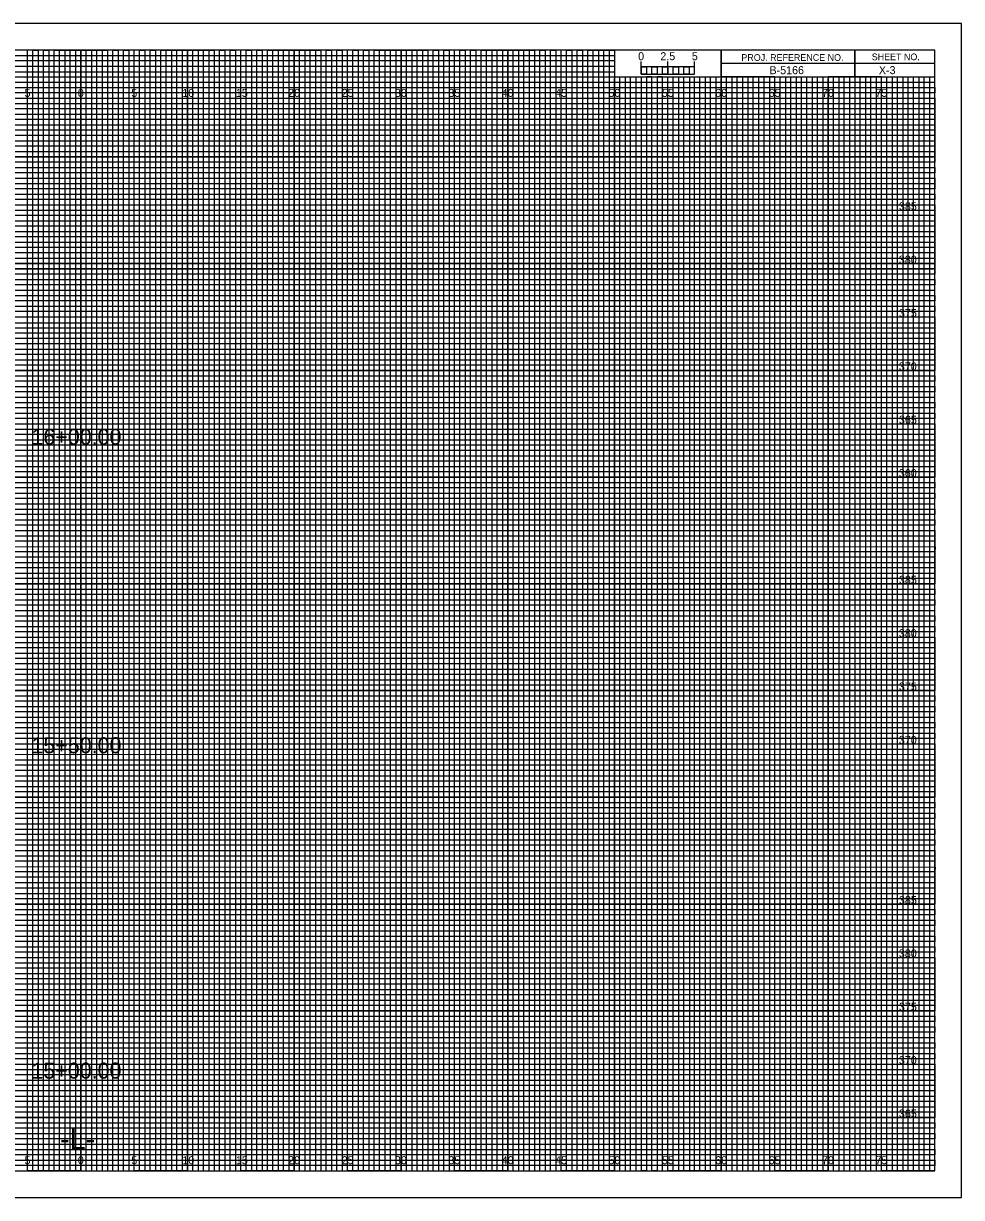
# Model space of a CAD drawing. Extents: x -8 to 162, y 218 to 328.
# Drawn here: x 74.6 to 162.5, y 217.5 to 327.5 of the extents above; entities that cross this region are included whole.
import ezdxf

# ---------------------------------------------------------------- set-up
doc = ezdxf.new("R2010")
doc.units = 0
for name, color, linetype in [('Cored Slab Unit CELL', 7, 'Continuous'), ('Exist XS Center Line Elevation Label', 7, 'Continuous'), ('Exist XS Ground Line', 7, 'Continuous'), ('Prop CMT Guardrail Graphics', 7, 'Continuous'), ('Prop CMT Pvmt Surface', 7, 'Continuous'), ('Prop CMT Pvmt Surface Shoulder', 7, 'Continuous'), ('Prop CMT Slope Grass', 7, 'Continuous'), ('Prop CMT Subgrade Earthwork', 7, 'Continuous'), ('Prop XS Berm Ditch', 7, 'Continuous'), ('Prop XS Finish Grade Earthwork', 7, 'Continuous'), ('Scratch_Level_0', 7, 'Continuous'), ('Scratch_Level_1', 7, 'Continuous'), ('Scratch_Level_2', 7, 'Continuous'), ('Sheet Cross Section Scale CELL', 7, 'Continuous'), ('Typical Curb CELL', 7, 'Continuous')]:
    doc.layers.add(name, color=color, linetype=linetype)

msp = doc.modelspace()

# ---------------------------------------------------------------- linework, layer by layer
at = {"layer": 'Exist XS Center Line Elevation Label'}
for points in [[(72.5, 220), (77.5, 220), (77.5, 325), (82.5, 325), (82.5, 220), (87.5, 220), (87.5, 325), (92.5, 325), (92.5, 220), (97.5, 220), (97.5, 325), (102.5, 325), (102.5, 220), (107.5, 220), (107.5, 325), (112.5, 325), (112.5, 220), (117.5, 220), (117.5, 325), (122.5, 325), (122.5, 220), (127.5, 220), (127.5, 325), (129.97, 325), (130, 325), (130, 322.5), (132.5, 322.5), (132.5, 220), (137.5, 220), (137.5, 322.5), (142.5, 322.5), (142.5, 220), (147.5, 220), (147.5, 322.5), (152.5, 322.5), (152.5, 220), (157.5, 220), (157.5, 322.5)], [(0, 322.5), (137.5, 322.5)], [(0, 312.5), (160, 312.5), (160, 317.5), (0, 317.5)], [(0, 302.5), (160, 302.5), (160, 307.5), (0, 307.5)], [(0, 292.5), (160, 292.5), (160, 297.5), (0, 297.5)], [(0, 282.5), (160, 282.5), (160, 287.5), (0, 287.5)], [(0, 272.5), (160, 272.5), (160, 277.5), (0, 277.5)], [(0, 262.5), (160, 262.5), (160, 267.5), (0, 267.5)], [(0, 252.5), (160, 252.5), (160, 257.5), (0, 257.5)], [(0, 242.5), (160, 242.5), (160, 247.5), (0, 247.5)], [(0, 232.5), (160, 232.5), (160, 237.5), (0, 237.5)], [(0, 222.5), (160, 222.5), (160, 227.5), (0, 227.5)]]:
    msp.add_lwpolyline(points, dxfattribs=at)
at = {"layer": 'Exist XS Ground Line'}
for p, q in [((75, 325), (70, 325)), ((75, 220), (75, 325)), ((85, 325), (80, 325)), ((80, 325), (80, 220)), ((85, 220), (85, 325)), ((95, 325), (90, 325)), ((90, 325), (90, 220)), ((95, 220), (95, 325)), ((105, 325), (100, 325)), ((100, 325), (100, 220)), ((105, 220), (105, 325)), ((115, 325), (110, 325)), ((110, 325), (110, 220)), ((115, 220), (115, 325)), ((125, 325), (120, 325)), ((120, 325), (120, 220)), ((125, 220), (125, 325)), ((130, 325), (130, 220)), ((135, 220), (135, 322.5)), ((145, 322.5), (140, 322.5)), ((140, 322.5), (140, 220)), ((145, 220), (145, 322.5)), ((155, 322.5), (150, 322.5)), ((150, 322.5), (150, 220)), ((155, 220), (155, 322.5)), ((80, 220), (75, 220)), ((90, 220), (85, 220)), ((100, 220), (95, 220)), ((110, 220), (105, 220)), ((120, 220), (115, 220)), ((130, 220), (125, 220)), ((140, 220), (135, 220)), ((150, 220), (145, 220)), ((160, 220), (155, 220)), ((160, 220), (160, 220))]:
    msp.add_line(p, q, dxfattribs=at)
for points in [[(0, 320), (160, 320), (160, 315), (0, 315)], [(0, 310), (160, 310), (160, 305), (0, 305)], [(0, 300), (160, 300), (160, 295), (0, 295)], [(0, 290), (160, 290), (160, 285), (0, 285)], [(0, 280), (160, 280), (160, 275), (0, 275)], [(0, 270), (160, 270), (160, 265), (0, 265)], [(0, 260), (160, 260), (160, 255), (0, 255)], [(0, 250), (160, 250), (160, 245), (0, 245)], [(0, 240), (160, 240), (160, 235), (0, 235)], [(0, 230), (160, 230), (160, 225), (0, 225)]]:
    msp.add_lwpolyline(points, dxfattribs=at)
at = {"layer": 'Prop CMT Subgrade Earthwork'}
msp.add_lwpolyline([(-7.5, 217.5), (162.5, 217.5), (162.5, 327.5), (-7.5, 327.5)], close=True, dxfattribs=at)
at = {"layer": 'Prop XS Berm Ditch'}
for p, q in [((0, 324.5), (130, 324.5)), ((130, 324.5), (130, 323.99)), ((130, 323.99), (0, 323.99)), ((0, 323.5), (130, 323.5)), ((130, 323.5), (130, 322.94)), ((130, 322.94), (0, 322.94)), ((0, 322), (160, 322))]:
    msp.add_line(p, q, dxfattribs=at)
for points in [[(0, 321.5), (135, 321.5), (160, 321.5), (160, 321), (0, 321)], [(0, 320.5), (160, 320.5), (160, 319.5), (0, 319.5)], [(0, 319), (160, 319), (160, 318.5), (0, 318.49)], [(0, 318), (160, 318), (160, 317), (0, 317)], [(0, 316.5), (160, 316.5), (160, 316), (0, 316)], [(0, 315.5), (160, 315.5), (160, 314.5), (0, 314.5)], [(0, 314), (160, 314), (160, 313.5), (0, 313.5)], [(0, 313), (160, 313), (160, 312), (0, 312)], [(0, 311.5), (160, 311.5), (160, 311), (0, 311)], [(0, 310.5), (160, 310.5), (160, 309.5), (0, 309.5)], [(0, 309), (160, 309), (160, 308.5), (0, 308.5)], [(0, 308), (160, 308), (160, 306.98), (160, 306.5), (160, 306), (0, 306)], [(0, 307), (160, 307), (160, 306.5), (0, 306.5)], [(0, 305.5), (160, 305.5), (160, 304.5), (0, 304.51)], [(0, 304.51), (160, 304.5), (160, 304), (0, 304)], [(0, 303.5), (160, 303.5), (160, 303), (0, 303)], [(0, 302), (160, 302), (160, 301.5), (0, 301.5)], [(0, 301), (160, 301), (160, 300.5), (0, 300.5)], [(-0.04, 299.44), (160, 299.44), (160, 298.94), (-0.04, 298.94)], [(0, 298.5), (160, 298.5), (160, 298), (0, 298)], [(0, 297), (160, 297), (160, 296.5), (0, 296.5)], [(0, 296), (160, 296), (160, 295.5), (0, 295.5)], [(0, 294.5), (160, 294.5), (160, 294), (0, 294)], [(0, 293.5), (160, 293.5), (160, 293), (0, 293)], [(0, 292), (160, 292), (160, 291.5), (0, 291.5)], [(0, 291), (160, 291), (160, 290.5), (0, 290.5)], [(0, 289.5), (160, 289.5), (160, 288.99), (0, 289)], [(0, 288.5), (160, 288.5), (160, 288), (0, 288)], [(0, 287), (160, 287), (160, 286.5), (0, 286.5)], [(0, 286), (160, 286), (160, 285.5), (0, 285.5)], [(0, 284.5), (160, 284.5), (160, 284), (0, 284)], [(0, 283.5), (160, 283.5), (160, 283), (0, 283)], [(0, 282), (160, 282), (160, 281.5), (0, 281.5)], [(0, 281), (160, 281), (160, 280.5), (0, 280.5)], [(0, 279.5), (160, 279.5), (160, 279), (0, 279)], [(0, 278.5), (160.03, 278.45), (160, 278), (0, 278)], [(0, 277), (160, 277), (160, 276.5), (0, 276.5)], [(0, 276), (160, 276), (160, 275.5), (0, 275.5)], [(0, 274.5), (160, 274.5), (160, 274), (0, 274)], [(0, 273.5), (160, 273.5), (160, 273), (0, 273)], [(0, 272), (160, 272), (160, 271.5), (0, 271.5)], [(0, 271), (160, 271), (160, 270.5), (0, 270.5)], [(0, 269.5), (160, 269.5), (160, 269), (0, 269)], [(0, 268.5), (160, 268.5), (160, 268), (0, 268)], [(0, 267), (160, 267), (160, 266.5), (0, 266.5)], [(0, 266), (160, 266), (160, 265.5), (0, 265.5)], [(0, 264.5), (160, 264.5), (160, 264), (0, 264)], [(0, 263.5), (160, 263.5), (160, 263), (0, 263)], [(0, 262), (160, 262), (160, 261.5), (0, 261.5)], [(0, 261), (160, 261), (160, 260.5), (0, 260.5)], [(0, 259.5), (160, 259.5), (160, 258.99), (0, 259)], [(0, 258.5), (160, 258.5), (160, 258), (0, 258)], [(0, 257), (160, 257), (160, 256.5), (0, 256.5)], [(0, 256), (160, 256), (160, 255.5), (0, 255.5)], [(0, 254.5), (160, 254.5), (160, 254), (0, 254)], [(0, 253.5), (160, 253.5), (160, 253), (0, 253)], [(0, 252), (160, 252), (160, 251.5), (0, 251.5)], [(0, 251), (160, 251), (160, 250.5), (0, 250.5)], [(0, 249.5), (160, 249.5), (160, 249), (0, 249)], [(0, 248.5), (160.03, 248.46), (160, 248), (0, 248)], [(0, 247), (160, 247), (160, 246.5), (0, 246.5)], [(0, 246), (160, 246), (160, 245.5), (0, 245.5)], [(0, 244.5), (160, 244.5), (160, 244), (0, 244)], [(0, 243.5), (160, 243.5), (160, 243), (0, 243)], [(0, 242), (160, 242), (160, 241.5), (0, 241.5)], [(0, 241), (160, 241), (160, 240.5), (0, 240.5)], [(0, 239.5), (160, 239.5), (160, 239), (0, 239)], [(0, 238.5), (160, 238.5), (160, 238), (0, 238)], [(0, 237), (160, 237), (160, 236.5), (0, 236.5)], [(0, 236), (160, 236), (160, 235.5), (0, 235.5)], [(0, 234.5), (160, 234.5), (160, 234), (0, 234)], [(0, 233.5), (160, 233.5), (160, 233), (0, 233)], [(0, 232), (160, 232), (160, 231.5), (0, 231.5)], [(0, 231), (160, 231), (160, 230.5), (0, 230.5)], [(0, 229.5), (160, 229.5), (160, 229), (0, 229)], [(0, 228.5), (160, 228.5), (160, 228), (0, 228)], [(0, 227), (160, 227), (160, 226.5), (0, 226.5)], [(0, 226), (160, 226), (160, 225.5), (0, 225.5)], [(0, 224.5), (160, 224.5), (160, 224), (0, 224)], [(0, 223.5), (160, 223.5), (160, 223), (0, 223)], [(0, 222), (160, 222), (160, 221.5), (0, 221.5)], [(0, 221), (160, 221), (160, 220.5), (0, 220.5)]]:
    msp.add_lwpolyline(points, dxfattribs=at)
at = {"layer": 'Scratch_Level_1'}
for p, q in [((133.5, 322.5), (133, 322.5)), ((133, 322.5), (133, 220)), ((133.5, 220), (133.5, 322.5)), ((134.5, 322.5), (134, 322.5)), ((134, 322.5), (134, 220)), ((134.5, 220), (134.5, 322.5)), ((133, 220), (132.5, 220)), ((134, 220), (133.5, 220))]:
    msp.add_line(p, q, dxfattribs=at)
for points in [[(75, 220), (75.5, 220), (75.5, 325), (76, 325), (76, 220)], [(76, 220), (76.5, 220), (76.5, 325), (77, 325), (77, 220)], [(77.5, 220), (78, 220), (78, 325), (78.5, 325), (78.5, 220)], [(78.5, 220), (79, 220), (79, 325), (79.5, 325), (79.5, 220)], [(80, 220), (80.5, 220), (80.5, 325), (81, 325), (81, 220)], [(81, 220), (81.5, 220), (81.5, 325), (82, 325), (82, 220)], [(82.5, 220), (83, 220), (83, 325), (83.5, 325), (83.5, 220)], [(83.5, 220), (84, 220), (84, 325), (84.5, 325), (84.5, 220)], [(85, 220), (85.5, 220), (85.5, 325), (86, 325), (86, 220)], [(86, 220), (86.5, 220), (86.5, 325), (87, 325), (87, 220)], [(87.5, 220), (88, 220), (88, 325), (88.5, 325), (88.5, 220)], [(88.5, 220), (89, 220), (89, 325), (89.5, 325), (89.5, 220)], [(90, 220), (90.5, 220), (90.5, 325), (91, 325), (91, 220)], [(91, 220), (91.5, 220), (91.5, 325), (92, 325), (92, 220)], [(92.5, 220), (93, 220), (93, 325), (93.5, 325), (93.5, 220)], [(93.5, 220), (94, 220), (94, 325), (94.5, 325), (94.5, 220)], [(95, 220), (95.5, 220), (95.5, 325), (96, 325), (96, 220)], [(96, 220), (96.5, 220), (96.5, 325), (97, 325), (97, 220)], [(97.5, 220), (98, 220), (98, 325), (98.5, 325), (98.5, 220)], [(98.5, 220), (99, 220), (99, 325), (99.5, 325), (99.5, 220)], [(100, 220), (100.5, 220), (100.5, 325), (101, 325), (101, 220)], [(101, 220), (101.5, 220), (101.5, 325), (102, 325), (102, 220)], [(102.5, 220), (103, 220), (103, 325), (103.5, 325), (103.5, 220)], [(103.5, 220), (104, 220), (104, 325), (104.5, 325), (104.5, 220)], [(105, 220), (105.5, 220), (105.5, 325), (106, 325), (106, 220)], [(106, 220), (106.5, 220), (106.5, 325), (107, 325), (107, 220)], [(107.5, 220), (108, 220), (108, 325), (108.5, 325), (108.5, 220)], [(108.5, 220), (109, 220), (109, 325), (109.5, 325), (109.5, 220)], [(110, 220), (110.5, 220), (110.5, 325), (111, 325), (111, 220)], [(111, 220), (111.5, 220), (111.5, 325), (112, 325), (112, 220)], [(112.5, 220), (113, 220), (113, 325), (113.5, 325), (113.5, 220)], [(113.5, 220), (114, 220), (114, 325), (114.5, 325), (114.5, 220)], [(115, 220), (115.5, 220), (115.5, 325), (116, 325), (116, 220)], [(116, 220), (116.5, 220), (116.5, 325), (117, 325), (117, 220)], [(117.5, 220), (118, 220), (118, 325), (118.5, 325), (118.5, 220)], [(118.5, 220), (119, 220), (119, 325), (119.5, 325), (119.5, 220)], [(120, 220), (120.5, 220), (120.5, 325), (121, 325), (121, 220)], [(121, 220), (121.5, 220), (121.5, 325), (122, 325), (122, 220)], [(122.5, 220), (123, 220), (123, 325), (123.5, 325), (123.5, 220)], [(123.5, 220), (124, 220), (124, 325), (124.5, 325), (124.5, 220)], [(125, 220), (125.5, 220), (125.5, 325), (126, 325), (126, 220)], [(126, 220), (126.5, 220), (126.5, 325), (127, 325), (127, 220)], [(127.5, 220), (128, 220), (128, 325), (128.5, 325), (128.5, 220)], [(128.5, 220), (129, 220), (129, 325), (129.5, 325), (129.5, 220)], [(130, 220), (130.5, 220), (130.5, 322.5), (131.01, 322.5), (131.01, 220)], [(131, 220), (131.5, 220), (131.5, 322.5), (132, 322.5), (132, 220)], [(135, 220), (135.49, 220), (135.49, 322.5), (136, 322.5), (136, 220)], [(136, 220), (136.5, 220), (136.5, 322.5), (137.03, 322.5), (137.03, 220)], [(137.5, 220), (138, 220), (138, 322.5), (138.5, 322.5), (138.5, 220)], [(138.5, 220), (139, 220), (139, 322.5), (139.5, 322.5), (139.5, 220)], [(140, 220), (140.5, 220), (140.5, 322.5), (141, 322.5), (141, 220)], [(141, 220), (141.5, 220), (141.5, 322.5), (142, 322.5), (142, 220)], [(142.5, 220), (143, 220), (143, 322.5), (143.5, 322.5), (143.5, 220)], [(143.5, 220), (144, 220), (144, 322.5), (144.5, 322.5), (144.5, 220)], [(145, 220), (145.5, 220), (145.5, 322.5), (146, 322.5), (146, 220)], [(146, 220), (146.5, 220), (146.5, 322.5), (147, 322.5), (147, 220)], [(147.5, 220), (148, 220), (148, 322.5), (148.5, 322.5), (148.5, 220)], [(148.5, 220), (149, 220), (149, 322.5), (149.5, 322.5), (149.5, 220)], [(150, 220), (150.5, 220), (150.5, 322.5), (151, 322.5), (151, 220)], [(151, 220), (151.5, 220), (151.5, 322.5), (152, 322.5), (152, 220)], [(152.5, 220), (153, 220), (153, 322.5), (153.5, 322.5), (153.5, 220)], [(153.5, 220), (154, 220), (154, 322.5), (154.5, 322.5), (154.5, 220)], [(155, 220), (155.5, 220), (155.5, 322.5), (156, 322.5), (156, 220)], [(156, 220), (156.5, 220), (156.5, 322.5), (157, 322.5), (157, 220)], [(157.5, 220), (158, 220), (158, 322.5), (158.5, 322.5), (158.5, 220)], [(158.5, 220), (159, 220), (159, 322.5), (159.5, 322.5), (159.5, 220)]]:
    msp.add_lwpolyline(points, dxfattribs=at)
at = {"layer": 'Scratch_Level_2'}
for p, q in [((75, 220), (75, 325)), ((80, 220), (80, 325)), ((85, 220), (85, 325)), ((90, 220), (90, 325)), ((95, 220), (95, 325)), ((100, 220), (100, 325)), ((105, 220), (105, 325)), ((110, 220), (110, 325)), ((115, 220), (115, 325)), ((120, 220), (120, 325)), ((125, 220), (125, 325)), ((130, 220), (130, 322.34)), ((135, 220), (135, 322.34)), ((140, 220), (140, 322.34)), ((145, 220), (145, 322.34)), ((150, 220), (150, 322.34)), ((155, 220), (155, 322.34)), ((0, 320), (160, 320)), ((0, 315), (160, 315)), ((0, 310), (160, 310)), ((0, 305), (160, 305)), ((0, 300), (160, 300)), ((0, 295), (160, 295)), ((0, 290), (160, 290)), ((0, 285), (160, 285)), ((0, 280), (160, 280)), ((0, 275), (160, 275)), ((0, 270), (160, 270)), ((0, 265), (160, 265)), ((0, 260), (160, 260)), ((0, 255), (160, 255)), ((0, 250), (160, 250)), ((0, 245), (160, 245)), ((0, 240), (160, 240)), ((0, 235), (160, 235)), ((0, 230), (160, 230)), ((0, 225), (160, 225))]:
    msp.add_line(p, q, dxfattribs=at)
at = {"layer": 'Sheet Cross Section Scale CELL'}
for p, q in [((132.5, 322.75), (132.5, 323.95)), ((132.5, 323.45), (132.5, 323.95)), ((135, 322.75), (135, 323.95)), ((137.5, 322.75), (137.5, 323.95)), ((137.5, 323.45), (137.5, 323.95))]:
    msp.add_line(p, q, dxfattribs=at)
for points in [[(137.5, 323.45), (132.5, 323.45), (132.5, 322.75), (137.5, 322.75)], [(132.5, 323.45), (133, 323.45), (133, 322.75), (132.5, 322.75)], [(133.5, 323.45), (134, 323.45), (134, 322.75), (133.5, 322.75)], [(134.5, 323.45), (135, 323.45), (135, 322.75), (134.5, 322.75)], [(135.5, 323.45), (136, 323.45), (136, 322.75), (135.5, 322.75)], [(136.5, 323.45), (137, 323.45), (137, 322.75), (136.5, 322.75)]]:
    msp.add_lwpolyline(points, close=True, dxfattribs=at)
at = {"layer": 'Typical Curb CELL'}
for p, q in [((152.5, 325), (152.5, 322.5)), ((152.5, 322.5), (152.5, 325)), ((160, 323.75), (140, 323.75)), ((140, 323.75), (140, 322.5)), ((140, 322.5), (160, 322.5))]:
    msp.add_line(p, q, dxfattribs=at)
for points in [[(160, 325), (0, 325), (0, 220), (160, 220)], [(140, 325), (130, 325), (130, 322.51), (140, 322.51)], [(160, 325), (140, 325), (140, 322.5), (160, 322.5)]]:
    msp.add_lwpolyline(points, close=True, dxfattribs=at)

# ---------------------------------------------------------------- texts
at = {"layer": 'Cored Slab Unit CELL'}
for s, p in [('2.5', (134.29, 324.06)), ('5', (137.24, 324.06))]:
    msp.add_text(s, height=0.75, dxfattribs=at).set_placement(p)
at = {"layer": 'Prop CMT Guardrail Graphics'}
msp.add_text('-L-', height=2, dxfattribs=at).set_placement((78.08, 222))
at = {"layer": 'Prop CMT Pvmt Surface'}
for s, p in [('385', (156.64, 310)), ('380', (156.63, 305)), ('375', (156.64, 300)), ('370', (156.63, 295)), ('365', (156.64, 290)), ('360', (156.63, 285)), ('385', (156.64, 275)), ('380', (156.63, 270)), ('375', (156.64, 265)), ('370', (156.63, 260)), ('385', (156.64, 245)), ('380', (156.63, 240)), ('375', (156.64, 235)), ('370', (156.63, 230)), ('365', (156.64, 225))]:
    msp.add_text(s, height=0.75, dxfattribs=at).set_placement(p)
at = {"layer": 'Prop CMT Pvmt Surface Shoulder'}
for s, p in [('16+00.00', (75.39, 288.03)), ('15+50.00', (75.39, 259.12)), ('15+00.00', (75.39, 228.64))]:
    msp.add_text(s, height=1.5, dxfattribs=at).set_placement(p)
at = {"layer": 'Prop CMT Slope Grass'}
msp.add_text('B-5166', height=0.75, dxfattribs=at).set_placement((144.51, 322.75))
at = {"layer": 'Prop XS Finish Grade Earthwork'}
msp.add_text('X-3', height=0.75, dxfattribs=at).set_placement((154.76, 322.75))
at = {"layer": 'Scratch_Level_0'}
for s, p in [('5', (74.74, 320.62)), ('0', (79.73, 320.62)), ('0', (79.73, 320.62)), ('5', (84.74, 320.62)), ('10', (89.52, 320.62)), ('15', (94.53, 320.62)), ('20', (99.43, 320.62)), ('25', (104.44, 320.62)), ('30', (109.43, 320.62)), ('35', (114.44, 320.62)), ('40', (119.43, 320.62)), ('45', (124.44, 320.62)), ('50', (129.43, 320.62)), ('55', (134.44, 320.62)), ('60', (139.43, 320.62)), ('65', (144.44, 320.62)), ('70', (149.43, 320.62)), ('75', (154.44, 320.62)), ('5', (74.74, 220.62)), ('0', (79.73, 220.62)), ('0', (79.73, 220.62)), ('5', (84.74, 220.62)), ('10', (89.52, 220.62)), ('15', (94.53, 220.62)), ('20', (99.43, 220.62)), ('25', (104.44, 220.62)), ('30', (109.43, 220.62)), ('35', (114.44, 220.62)), ('40', (119.43, 220.62)), ('45', (124.44, 220.62)), ('50', (129.43, 220.62)), ('55', (134.44, 220.62)), ('60', (139.43, 220.62)), ('65', (144.44, 220.62)), ('70', (149.43, 220.62)), ('75', (154.44, 220.62))]:
    msp.add_text(s, height=0.75, dxfattribs=at).set_placement(p)
at = {"layer": 'Sheet Cross Section Scale CELL'}
msp.add_text('0', height=0.75, dxfattribs=at).set_placement((132.21, 324.06))
at = {"layer": 'Typical Curb CELL'}
for s, p in [('PROJ. REFERENCE NO.', (141.88, 324)), ('SHEET NO.', (154.09, 324.06))]:
    msp.add_text(s, height=0.625, dxfattribs=at).set_placement(p)

doc.saveas('drawing.dxf')
